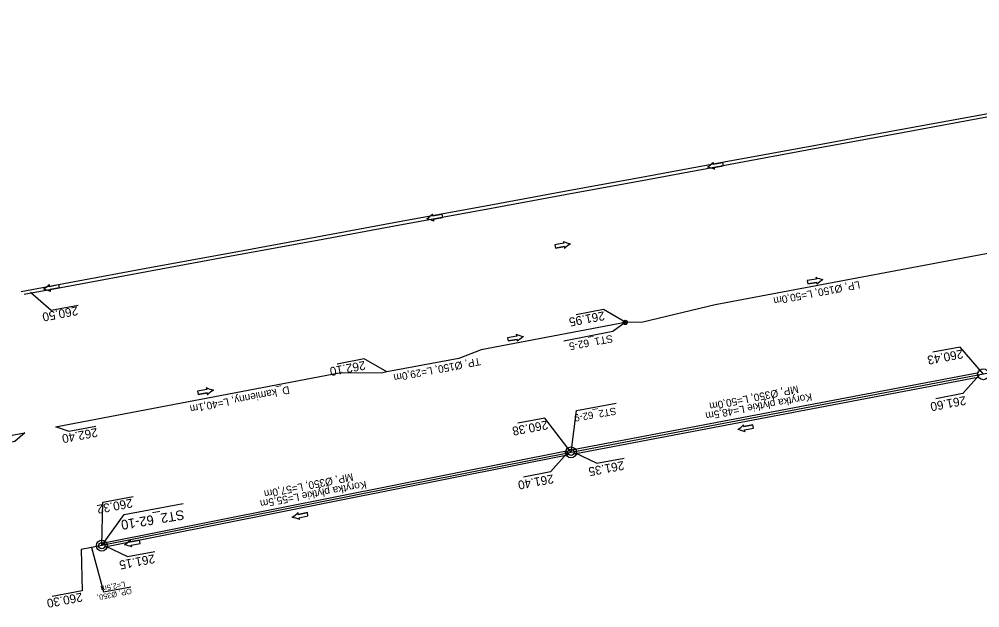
# Model space of a CAD drawing. Extents: x -1 to 65640748, y -22 to 5530284.
# Drawn here: x 6556683.1 to 6556797.5, y 5528515.8 to 5528585.9 of the extents above; entities that cross this region are included whole.
import ezdxf

# ---------------------------------------------------------------- set-up
doc = ezdxf.new("R2010")
doc.units = 0
for name, color, linetype in [('TOR_PROF-studnie i osadniki', 7, 'Continuous'), ('TOR_PS_ODW-drenaze', 7, 'Continuous'), ('TOR_PS_ODW-drenokolektory', 7, 'Continuous'), ('TOR_PS_ODW-kolektory', 7, 'Continuous'), ('TOR_PS_ODW-studnie PEHD', 7, 'Continuous'), ('TOR_PS_OPIS_O-opisy rurociagow', 7, 'Continuous'), ('TOR_PS_OPIS_O-opisy studni', 7, 'Continuous'), ('TOR_PS_OPIS_T-INFO', 7, 'Continuous'), ('TOR_PS_T-rowy otwarte umocnione', 7, 'Continuous')]:
    doc.layers.add(name, color=color, linetype=linetype)

msp = doc.modelspace()

# ---------------------------------------------------------------- linework, layer by layer
at = {"layer": 'TOR_PROF-studnie i osadniki'}
for centre, radius in [((6556755.29, 5528549.81), 0.25), ((6556755.29, 5528549.81), 0.125), ((6556797.95, 5528543.64), 0.65), ((6556748.83, 5528534.33), 0.65), ((6556748.83, 5528534.33), 0.375), ((6556692.92, 5528523.23), 0.65), ((6556692.92, 5528523.23), 0.375)]:
    msp.add_circle(centre, radius, dxfattribs=at)
at = {"layer": 'TOR_PS_ODW-drenaze'}
for points in [[(6556755.29, 5528549.81), (6556738.13, 5528546.55), (6556735.44, 5528545.53), (6556726.88, 5528543.91)], [(6556726.88, 5528543.91), (6556726.4, 5528543.82), (6556721.22, 5528543.75), (6556687.41, 5528537.35)], [(6556683.7, 5528536.64), (6556675.44, 5528535.08), (6556670.59, 5528533.24), (6556654.08, 5528530.11), (6556648.9, 5528530.05), (6556639.49, 5528528.26)]]:
    msp.add_lwpolyline(points, dxfattribs=at)
at = {"layer": 'TOR_PS_ODW-drenokolektory'}
for points in [[(6556896.02, 5528563.25), (6556846.99, 5528553.45), (6556797.95, 5528543.64), (6556748.83, 5528534.33), (6556692.92, 5528523.23)], [(6556896.02, 5528563.25), (6556846.99, 5528553.45), (6556797.95, 5528543.64), (6556748.83, 5528534.33)], [(6556804.42, 5528559.12), (6556766.01, 5528551.9), (6556757.4, 5528549.85), (6556755.29, 5528549.81)]]:
    msp.add_lwpolyline(points, dxfattribs=at)
at = {"layer": 'TOR_PS_ODW-kolektory'}
msp.add_line((6556692.92, 5528523.23), (6556690.46, 5528522.76), dxfattribs=at)
msp.add_lwpolyline([(6556692.92, 5528523.23), (6556690.46, 5528522.76)], dxfattribs=at)
at = {"layer": 'TOR_PS_ODW-studnie PEHD'}
for radius in [0.25, 0.112]:
    msp.add_circle((6556755.29, 5528549.81), radius, dxfattribs=at)
at = {"layer": 'TOR_PS_OPIS_O-opisy rurociagow'}
for p, q in [((6556765.8, 5528568.64), (6556766.88, 5528568.84)), ((6556765.8, 5528568.64), (6556766.88, 5528568.84)), ((6556766.88, 5528568.84), (6556766.95, 5528568.45)), ((6556766.88, 5528568.84), (6556766.95, 5528568.45)), ((6556766.95, 5528568.45), (6556765.88, 5528568.25)), ((6556765.88, 5528568.25), (6556766.95, 5528568.45)), ((6556732.36, 5528562.49), (6556733.43, 5528562.69)), ((6556732.36, 5528562.49), (6556733.43, 5528562.69)), ((6556733.51, 5528562.3), (6556732.43, 5528562.1)), ((6556732.43, 5528562.1), (6556733.51, 5528562.3)), ((6556733.43, 5528562.69), (6556733.51, 5528562.3)), ((6556733.43, 5528562.69), (6556733.51, 5528562.3)), ((6556747.97, 5528559.23), (6556746.89, 5528559.04)), ((6556747.97, 5528559.23), (6556746.89, 5528559.04)), ((6556746.89, 5528559.04), (6556746.96, 5528558.65)), ((6556746.89, 5528559.04), (6556746.96, 5528558.65)), ((6556746.96, 5528558.65), (6556748.04, 5528558.84)), ((6556748.04, 5528558.84), (6556746.96, 5528558.65)), ((6556686.68, 5528554.1), (6556687.75, 5528554.31)), ((6556686.68, 5528554.1), (6556687.75, 5528554.31)), ((6556687.75, 5528554.31), (6556687.83, 5528553.91)), ((6556687.75, 5528554.31), (6556687.83, 5528553.91)), ((6556778.05, 5528554.97), (6556776.97, 5528554.78)), ((6556778.05, 5528554.97), (6556776.97, 5528554.78)), ((6556776.97, 5528554.78), (6556777.04, 5528554.39)), ((6556776.97, 5528554.78), (6556777.04, 5528554.39)), ((6556777.04, 5528554.39), (6556778.12, 5528554.57)), ((6556778.12, 5528554.57), (6556777.04, 5528554.39)), ((6556687.83, 5528553.91), (6556686.75, 5528553.71)), ((6556686.75, 5528553.71), (6556687.83, 5528553.91)), ((6556742.35, 5528548.18), (6556741.27, 5528547.99)), ((6556742.35, 5528548.18), (6556741.27, 5528547.99)), ((6556741.27, 5528547.99), (6556741.34, 5528547.6)), ((6556741.27, 5528547.99), (6556741.34, 5528547.6)), ((6556741.34, 5528547.6), (6556742.42, 5528547.79)), ((6556742.42, 5528547.79), (6556741.34, 5528547.6)), ((6556705.42, 5528541.82), (6556704.34, 5528541.64)), ((6556705.42, 5528541.82), (6556704.34, 5528541.64)), ((6556704.34, 5528541.64), (6556704.41, 5528541.24)), ((6556704.34, 5528541.64), (6556704.41, 5528541.24)), ((6556704.41, 5528541.24), (6556705.49, 5528541.43)), ((6556705.49, 5528541.43), (6556704.41, 5528541.24)), ((6556770.47, 5528537.6), (6556769.4, 5528537.4)), ((6556769.4, 5528537.4), (6556770.47, 5528537.6)), ((6556769.48, 5528537), (6556770.55, 5528537.21)), ((6556769.48, 5528537), (6556770.55, 5528537.21)), ((6556770.55, 5528537.21), (6556770.47, 5528537.6)), ((6556770.55, 5528537.21), (6556770.47, 5528537.6)), ((6556717.41, 5528527.16), (6556716.34, 5528526.95)), ((6556716.34, 5528526.95), (6556717.41, 5528527.16)), ((6556716.41, 5528526.56), (6556717.48, 5528526.77)), ((6556716.41, 5528526.56), (6556717.48, 5528526.77)), ((6556717.48, 5528526.77), (6556717.41, 5528527.16)), ((6556717.48, 5528526.77), (6556717.41, 5528527.16)), ((6556697.43, 5528523.9), (6556696.35, 5528523.69)), ((6556696.35, 5528523.69), (6556697.43, 5528523.9)), ((6556696.43, 5528523.29), (6556697.5, 5528523.5)), ((6556696.43, 5528523.29), (6556697.5, 5528523.5)), ((6556697.5, 5528523.5), (6556697.43, 5528523.9)), ((6556697.5, 5528523.5), (6556697.43, 5528523.9))]:
    msp.add_line(p, q, dxfattribs=at)
for points in [[(6556765.77, 5528568.87), (6556765.77, 5528568.87)], [(6556765.93, 5528568.03), (6556765.93, 5528568.03)], [(6556732.33, 5528562.71), (6556732.33, 5528562.71)], [(6556732.48, 5528561.88), (6556732.48, 5528561.88)], [(6556747.92, 5528559.45), (6556747.92, 5528559.45)], [(6556748.07, 5528558.61), (6556748.07, 5528558.61)], [(6556778, 5528555.19), (6556778, 5528555.19)], [(6556686.65, 5528554.33), (6556686.65, 5528554.33)], [(6556778.14, 5528554.35), (6556778.14, 5528554.35)], [(6556686.81, 5528553.49), (6556686.81, 5528553.49)], [(6556742.3, 5528548.4), (6556742.3, 5528548.4)], [(6556742.45, 5528547.56), (6556742.45, 5528547.56)], [(6556705.37, 5528542.04), (6556705.37, 5528542.04)], [(6556705.52, 5528541.2), (6556705.52, 5528541.2)], [(6556769.37, 5528537.62), (6556769.37, 5528537.62)], [(6556769.53, 5528536.78), (6556769.53, 5528536.78)], [(6556716.3, 5528527.17), (6556716.3, 5528527.17)], [(6556716.46, 5528526.34), (6556716.46, 5528526.34)], [(6556696.32, 5528523.91), (6556696.32, 5528523.91)], [(6556696.48, 5528523.07), (6556696.48, 5528523.07)]]:
    msp.add_lwpolyline(points, dxfattribs=at)
for centre, radius, start, end in [((6556762.33, 5528572.38), 4.92, 303.9767, 314.3585), ((6556762.33, 5528572.38), 4.92, 303.9767, 314.3585), ((6556765.35, 5528568.69), 0.458, 353.7827, 22.244), ((6556765.35, 5528568.69), 0.458, 353.7827, 22.244), ((6556764, 5528563.51), 4.92, 66.9388, 77.3206), ((6556764, 5528563.51), 4.92, 66.9388, 77.3206), ((6556765.47, 5528568.04), 0.458, 359.0534, 27.5146), ((6556765.47, 5528568.04), 0.458, 359.0534, 27.5146), ((6556728.89, 5528566.23), 4.92, 303.9767, 314.3585), ((6556728.89, 5528566.23), 4.92, 303.9767, 314.3585), ((6556730.56, 5528557.35), 4.92, 66.9388, 77.3206), ((6556730.56, 5528557.35), 4.92, 66.9388, 77.3206), ((6556731.9, 5528562.54), 0.458, 353.7827, 22.244), ((6556731.9, 5528562.54), 0.458, 353.7827, 22.244), ((6556732.03, 5528561.89), 0.458, 359.0534, 27.5146), ((6556732.03, 5528561.89), 0.458, 359.0534, 27.5146), ((6556749.91, 5528563.95), 4.92, 246.1449, 256.5268), ((6556748.38, 5528559.44), 0.458, 178.2595, 206.7208), ((6556749.91, 5528563.95), 4.92, 246.1449, 256.5268), ((6556748.38, 5528559.44), 0.458, 178.2595, 206.7208), ((6556748.49, 5528558.78), 0.458, 172.9889, 201.4501), ((6556748.49, 5528558.78), 0.458, 172.9889, 201.4501), ((6556751.45, 5528555.05), 4.92, 123.1828, 133.5647), ((6556751.45, 5528555.05), 4.92, 123.1828, 133.5647), ((6556779.99, 5528559.68), 4.92, 246.1449, 256.5268), ((6556778.46, 5528555.17), 0.458, 178.2595, 206.7208), ((6556779.99, 5528559.68), 4.92, 246.1449, 256.5268), ((6556778.46, 5528555.17), 0.458, 178.2595, 206.7208), ((6556683.21, 5528557.84), 4.92, 303.9767, 314.3585), ((6556683.21, 5528557.84), 4.92, 303.9767, 314.3585), ((6556686.22, 5528554.15), 0.458, 353.7827, 22.244), ((6556686.22, 5528554.15), 0.458, 353.7827, 22.244), ((6556778.57, 5528554.52), 0.458, 172.9889, 201.4501), ((6556778.57, 5528554.52), 0.458, 172.9889, 201.4501), ((6556781.53, 5528550.79), 4.92, 123.1828, 133.5647), ((6556781.53, 5528550.79), 4.92, 123.1828, 133.5647), ((6556684.88, 5528548.97), 4.92, 66.9388, 77.3206), ((6556684.88, 5528548.97), 4.92, 66.9388, 77.3206), ((6556686.35, 5528553.5), 0.458, 359.0534, 27.5146), ((6556686.35, 5528553.5), 0.458, 359.0534, 27.5146), ((6556744.29, 5528552.9), 4.92, 246.1449, 256.5268), ((6556742.76, 5528548.39), 0.458, 178.2595, 206.7208), ((6556744.29, 5528552.9), 4.92, 246.1449, 256.5268), ((6556742.76, 5528548.39), 0.458, 178.2595, 206.7208), ((6556742.87, 5528547.73), 0.458, 172.9889, 201.4501), ((6556742.87, 5528547.73), 0.458, 172.9889, 201.4501), ((6556745.84, 5528544), 4.92, 123.1828, 133.5647), ((6556745.84, 5528544), 4.92, 123.1828, 133.5647), ((6556707.36, 5528546.54), 4.92, 246.1449, 256.5268), ((6556705.83, 5528542.03), 0.458, 178.2595, 206.7208), ((6556707.36, 5528546.54), 4.92, 246.1449, 256.5268), ((6556705.83, 5528542.03), 0.458, 178.2595, 206.7208), ((6556705.94, 5528541.37), 0.458, 172.9889, 201.4501), ((6556705.94, 5528541.37), 0.458, 172.9889, 201.4501), ((6556708.91, 5528537.64), 4.92, 123.1828, 133.5647), ((6556708.91, 5528537.64), 4.92, 123.1828, 133.5647), ((6556765.91, 5528541.11), 4.92, 304.3278, 314.7097), ((6556765.91, 5528541.11), 4.92, 304.3278, 314.7097), ((6556767.63, 5528532.25), 4.92, 67.2899, 77.6718), ((6556767.63, 5528532.25), 4.92, 67.2899, 77.6718), ((6556768.94, 5528537.44), 0.458, 354.1339, 22.5951), ((6556768.94, 5528537.44), 0.458, 354.1339, 22.5951), ((6556769.07, 5528536.79), 0.458, 359.4045, 27.8657), ((6556769.07, 5528536.79), 0.458, 359.4045, 27.8657), ((6556712.84, 5528530.67), 4.92, 304.3278, 314.7097), ((6556712.84, 5528530.67), 4.92, 304.3278, 314.7097), ((6556714.57, 5528521.8), 4.92, 67.2899, 77.6718), ((6556714.57, 5528521.8), 4.92, 67.2899, 77.6718), ((6556715.88, 5528527), 0.458, 354.1339, 22.5951), ((6556715.88, 5528527), 0.458, 354.1339, 22.5951), ((6556716.01, 5528526.34), 0.458, 359.4045, 27.8657), ((6556716.01, 5528526.34), 0.458, 359.4045, 27.8657), ((6556692.85, 5528527.4), 4.92, 304.4267, 314.8085), ((6556692.85, 5528527.4), 4.92, 304.4267, 314.8085), ((6556694.59, 5528518.53), 4.92, 67.3888, 77.7707), ((6556694.59, 5528518.53), 4.92, 67.3888, 77.7707), ((6556695.9, 5528523.73), 0.458, 354.2327, 22.694), ((6556695.9, 5528523.73), 0.458, 354.2327, 22.694), ((6556696.03, 5528523.08), 0.458, 359.5034, 27.9646), ((6556696.03, 5528523.08), 0.458, 359.5034, 27.9646)]:
    msp.add_arc(centre, radius, start, end, dxfattribs=at)
at = {"layer": 'TOR_PS_OPIS_T-INFO'}
for points in [[(6556684.44, 5528553.42), (6556686.87, 5528551.27), (6556690.11, 5528551.87)], [(6556755.37, 5528549.79), (6556752.68, 5528551.35), (6556749.45, 5528550.73)], [(6556755.29, 5528549.81), (6556753.82, 5528548.71), (6556747.97, 5528547.58)], [(6556797.95, 5528543.64), (6556795.17, 5528546.87), (6556791.93, 5528546.25)], [(6556726.88, 5528543.91), (6556724.19, 5528545.47), (6556720.96, 5528544.85)], [(6556797.47, 5528543.54), (6556795.51, 5528541.33), (6556792.27, 5528540.71)], [(6556748.83, 5528534.33), (6556749.46, 5528539.31), (6556754.19, 5528540.19)], [(6556748.83, 5528534.32), (6556745.7, 5528538.42), (6556742.47, 5528537.8)], [(6556687.49, 5528537.36), (6556688.98, 5528536.85), (6556692.22, 5528537.46)], [(6556683.74, 5528536.65), (6556682.54, 5528535.63), (6556679.3, 5528535.01)], [(6556748.34, 5528534.22), (6556746.38, 5528532), (6556743.15, 5528531.38)], [(6556749.23, 5528534.33), (6556751.9, 5528533.05), (6556755.14, 5528533.65)], [(6556692.92, 5528523.23), (6556693.04, 5528528.41), (6556696.65, 5528529.08)], [(6556692.92, 5528523.23), (6556695.59, 5528526.92), (6556702.63, 5528528.23)], [(6556691.7, 5528523.03), (6556693.12, 5528517.73), (6556696.36, 5528518.33)], [(6556693.32, 5528523.22), (6556695.99, 5528521.94), (6556699.23, 5528522.55)], [(6556690.46, 5528522.76), (6556690.59, 5528517.87), (6556686.99, 5528517.18)]]:
    msp.add_lwpolyline(points, dxfattribs=at)
at = {"layer": 'TOR_PS_T-rowy otwarte umocnione'}
for p, q in [((6556797.21, 5528543.76), (6556749.09, 5528534.64)), ((6556748.29, 5528534.48), (6556693.18, 5528523.53))]:
    msp.add_line(p, q, dxfattribs=at)
for points in [[(6556856.1, 5528585.91), (6556846.33, 5528583.75), (6556836.51, 5528581.87), (6556826.69, 5528579.99), (6556816.87, 5528578.11), (6556807.04, 5528576.24), (6556797.21, 5528574.42), (6556787.37, 5528572.62), (6556777.54, 5528570.81), (6556767.7, 5528569), (6556757.87, 5528567.19), (6556748.03, 5528565.38), (6556738.2, 5528563.57), (6556728.36, 5528561.77), (6556718.53, 5528559.96), (6556708.69, 5528558.15), (6556698.86, 5528556.34), (6556689.02, 5528554.53), (6556683.31, 5528553.46)], [(6556856.18, 5528585.51), (6556846.41, 5528583.35), (6556836.59, 5528581.48), (6556826.76, 5528579.6), (6556816.94, 5528577.72), (6556807.12, 5528575.84), (6556797.28, 5528574.03), (6556787.45, 5528572.22), (6556777.61, 5528570.42), (6556767.78, 5528568.61), (6556757.94, 5528566.8), (6556748.11, 5528564.99), (6556738.27, 5528563.18), (6556728.44, 5528561.37), (6556718.6, 5528559.57), (6556708.77, 5528557.76), (6556698.93, 5528555.95), (6556689.1, 5528554.14), (6556683.68, 5528553.12)], [(6556797.21, 5528543.76), (6556797.3, 5528543.27), (6556749.18, 5528534.14)], [(6556748.29, 5528534.48), (6556748.39, 5528533.99), (6556693.28, 5528523.04)]]:
    msp.add_lwpolyline(points, dxfattribs=at)

# ---------------------------------------------------------------- texts
at = {"layer": 'TOR_PS_OPIS_O-opisy rurociagow'}
for s, height, rotation, p in [('LP, Ø150, L=50,0m', 0.9, 190.9157, (6556783.16, 5528554.75)), ('TP, Ø150, L=29,0m', 0.9, 190.9157, (6556737.96, 5528545.62)), ('D_kamienny, L=40,1m', 0.9, 191.128, (6556715.2, 5528542.23)), ('Korytka płytkie L=48,5m', 0.9, 190.3457, (6556777.45, 5528541.39)), ('MP, Ø350, L=50,0m', 0.9, 191.184, (6556775.84, 5528542.32)), ('MP, Ø350, L=57,0m', 0.9, 191.184, (6556722.78, 5528531.87)), ('Korytka płytkie L=55,5m', 0.9, 190.3457, (6556724.38, 5528530.94)), ('L=2,5m', 0.642, 191.35, (6556695.65, 5528518.98)), ('OP, Ø350, ', 0.642, 191.35, (6556696.42, 5528518.15))]:
    msp.add_text(s, height=height, rotation=rotation, dxfattribs=at).set_placement(p)
at = {"layer": 'TOR_PS_OPIS_O-opisy studni'}
for s, height, rotation, p in [('ST1_62-5', 0.9, 190.5101, (6556753.72, 5528548.34)), ('ST2_62-9', 0.863, 189.828, (6556754.13, 5528539.69)), ('ST2_62-10', 1.15, 189.5794, (6556702.64, 5528527.5))]:
    msp.add_text(s, height=height, rotation=rotation, dxfattribs=at).set_placement(p)
at = {"layer": 'TOR_PS_OPIS_T-INFO'}
for s, rotation, p in [('260.50', 190.7506, (6556689.98, 5528551.73)), ('261.95', 190.7159, (6556752.73, 5528551.13)), ('260.43', 190.7159, (6556795.43, 5528546.59)), ('262.10', 190.7159, (6556724.23, 5528545.24)), ('261.60', 190.7159, (6556795.78, 5528541.05)), ('260.38', 190.7159, (6556745.97, 5528538.14)), ('262.40', 190.7506, (6556692.32, 5528537.25)), ('261.35', 190.7506, (6556755.05, 5528533.32)), ('261.40', 190.7159, (6556746.65, 5528531.72)), ('260.32', 190.7506, (6556696.48, 5528528.84)), ('261.15', 190.7506, (6556699.14, 5528522.21)), ('260.30', 190.7159, (6556690.52, 5528517.64))]:
    msp.add_text(s, height=1.05, rotation=rotation, dxfattribs=at).set_placement(p)

doc.saveas('drawing.dxf')
